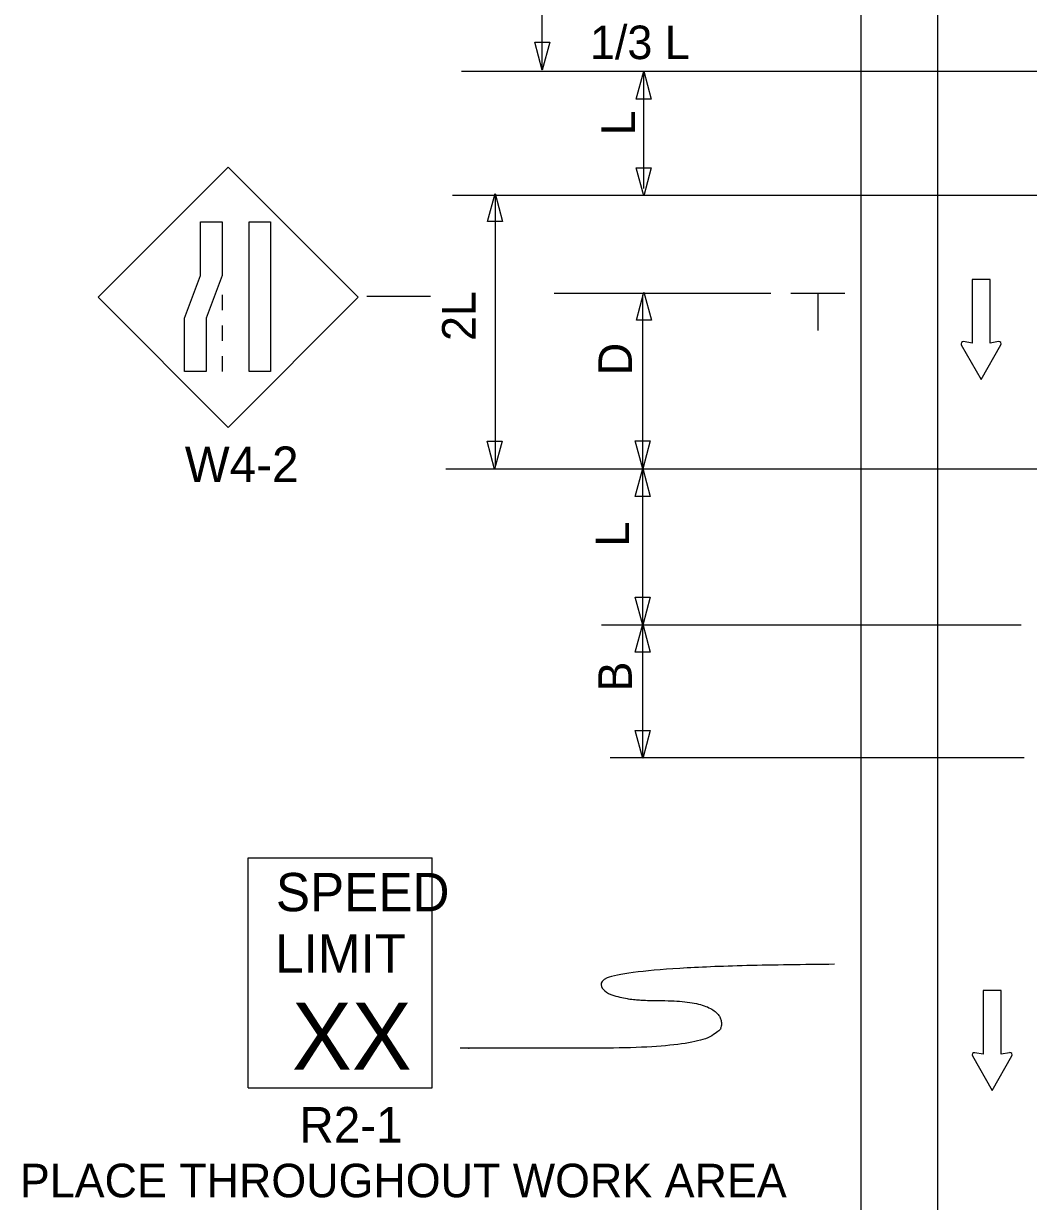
# Model space of a CAD drawing. Extents: x 20837 to 23689, y 414 to 2167.
# Drawn here: x 20938.5 to 21148.4, y 1033.1 to 1279 of the extents above; entities that cross this region are included whole.
import ezdxf

# ---------------------------------------------------------------- set-up
doc = ezdxf.new("R2010")
doc.units = 0
for name, color, linetype in [('MT_SCRATCH_LEVEL_E', 7, 'Continuous'), ('PAVT_EDGE_EX', 7, 'Continuous'), ('TRAFFIC_SIGNS_PR', 7, 'Continuous'), ('TYPICAL_EX', 7, 'Continuous'), ('TYPICAL_TEXT_DIMEN_PR', 7, 'Continuous')]:
    doc.layers.add(name, color=color, linetype=linetype)

msp = doc.modelspace()

# ---------------------------------------------------------------- linework, layer by layer
at = {"layer": 'MT_SCRATCH_LEVEL_E'}
for p, q in [((21140.37, 1225.58), (21136.63, 1225.58)), ((21136.63, 1225.58), (21136.63, 1212.32)), ((21140.37, 1225.58), (21136.63, 1225.58)), ((21136.63, 1225.58), (21136.63, 1212.32)), ((21140.37, 1212.32), (21140.37, 1225.58)), ((21140.37, 1212.32), (21140.37, 1225.58)), ((21136.63, 1212.32), (21134.85, 1212.64)), ((21136.63, 1212.32), (21134.85, 1212.64)), ((21142.15, 1212.64), (21140.37, 1212.32)), ((21142.15, 1212.64), (21140.37, 1212.32)), ((21134.37, 1211.95), (21138.52, 1204.71)), ((21134.37, 1211.95), (21138.52, 1204.71)), ((21138.52, 1204.71), (21142.63, 1211.95)), ((21138.52, 1204.71), (21142.63, 1211.95)), ((21142.68, 1077.11), (21138.94, 1077.11)), ((21138.94, 1077.11), (21138.94, 1063.85)), ((21142.68, 1077.11), (21138.94, 1077.11)), ((21138.94, 1077.11), (21138.94, 1063.85)), ((21142.68, 1063.85), (21142.68, 1077.11)), ((21142.68, 1063.85), (21142.68, 1077.11)), ((21136.69, 1063.48), (21140.83, 1056.24)), ((21136.69, 1063.48), (21140.83, 1056.24)), ((21138.94, 1063.85), (21137.17, 1064.16)), ((21138.94, 1063.85), (21137.17, 1064.16)), ((21140.83, 1056.24), (21144.94, 1063.48)), ((21140.83, 1056.24), (21144.94, 1063.48)), ((21144.46, 1064.16), (21142.68, 1063.85)), ((21144.46, 1064.16), (21142.68, 1063.85))]:
    msp.add_line(p, q, dxfattribs=at)
for centre, start, end in [((21134.78, 1212.18), 80.0362, 209.7731), ((21134.78, 1212.18), 80.0362, 209.7731), ((21142.22, 1212.18), 330.4248, 99.9638), ((21142.22, 1212.18), 330.4248, 99.9638), ((21137.09, 1063.7), 80.0362, 209.7731), ((21137.09, 1063.7), 80.0362, 209.7731), ((21144.54, 1063.71), 330.4248, 99.9638), ((21144.54, 1063.71), 330.4248, 99.9638)]:
    msp.add_arc(centre, 0.463, start, end, dxfattribs=at)
at = {"layer": 'PAVT_EDGE_EX'}
msp.add_line((21129.4, 1637.35), (21129.4, 831.94), dxfattribs=at)
at = {"layer": 'TRAFFIC_SIGNS_PR'}
for p, q in [((20981.2, 1249.03), (20954.05, 1221.88)), ((21008.35, 1221.88), (20981.2, 1249.03)), ((20979.95, 1222.37), (20979.95, 1219.17)), ((20954.05, 1221.88), (20981.2, 1194.73)), ((20981.2, 1194.73), (21008.35, 1221.88)), ((20979.95, 1215.97), (20979.95, 1212.77)), ((20979.95, 1209.57), (20979.95, 1206.37)), ((20985.42, 1104.82), (21023.82, 1104.82)), ((20985.42, 1056.82), (20985.42, 1104.82)), ((21023.82, 1056.82), (21023.82, 1104.82)), ((20985.42, 1056.82), (21023.82, 1056.82))]:
    msp.add_line(p, q, dxfattribs=at)
for points in [[(20979.95, 1237.62), (20979.95, 1226.44), (20976.61, 1217.55), (20976.61, 1206.37), (20972.11, 1206.37), (20972.11, 1217.55), (20975.46, 1226.44), (20975.46, 1237.62)], [(20990.09, 1237.62), (20990.09, 1206.37), (20985.6, 1206.37), (20985.6, 1237.62)]]:
    msp.add_lwpolyline(points, close=True, dxfattribs=at)
at = {"layer": 'TYPICAL_EX'}
msp.add_line((21113.4, 1637.05), (21113.4, 832.24), dxfattribs=at)
at = {"layer": 'TYPICAL_TEXT_DIMEN_PR'}
for p, q in [((21046.82, 1269.4), (21046.82, 1315.73)), ((21046.83, 1269.28), (21045.26, 1275.14)), ((21045.26, 1275.14), (21046.83, 1275.14)), ((21046.83, 1275.14), (21048.4, 1275.14)), ((21048.4, 1275.14), (21046.83, 1269.28)), ((21029.98, 1269.09), (21194.1, 1269.09)), ((21066.47, 1263.27), (21068.04, 1269.13)), ((21068.04, 1269.13), (21069.61, 1263.27)), ((21068.04, 1244.6), (21068.04, 1268.71)), ((21068.04, 1263.27), (21066.47, 1263.27)), ((21069.61, 1263.27), (21068.04, 1263.27)), ((21068.04, 1243.09), (21066.47, 1248.95)), ((21066.47, 1248.95), (21068.04, 1248.95)), ((21068.04, 1248.95), (21069.61, 1248.95)), ((21069.61, 1248.95), (21068.04, 1243.09)), ((21028.1, 1243.22), (21170.08, 1243.22)), ((21035.42, 1237.68), (21036.99, 1243.55)), ((21036.99, 1243.55), (21038.56, 1237.68)), ((21037, 1243.27), (21037, 1186.4)), ((21036.99, 1237.68), (21035.42, 1237.68)), ((21038.56, 1237.68), (21036.99, 1237.68)), ((21049.32, 1222.75), (21094.58, 1222.75)), ((21066.49, 1217.12), (21068.06, 1222.98)), ((21068.06, 1222.98), (21069.63, 1217.12)), ((21098.77, 1222.75), (21110.02, 1222.75)), ((21104.39, 1222.75), (21104.39, 1214.97)), ((21010.2, 1222.13), (21023.48, 1222.13)), ((21067.83, 1185.99), (21067.83, 1222.3)), ((21068.06, 1217.12), (21066.49, 1217.12)), ((21069.63, 1217.12), (21068.06, 1217.12)), ((21036.88, 1185.98), (21035.31, 1191.84)), ((21035.31, 1191.84), (21036.88, 1191.84)), ((21036.88, 1191.84), (21038.45, 1191.84)), ((21038.45, 1191.84), (21036.88, 1185.98)), ((21067.84, 1186.08), (21066.27, 1191.94)), ((21066.27, 1191.94), (21067.84, 1191.94)), ((21067.84, 1191.94), (21069.41, 1191.94)), ((21069.41, 1191.94), (21067.84, 1186.08)), ((21026.68, 1186.1), (21171.95, 1186.1)), ((21066.27, 1180.26), (21067.84, 1186.12)), ((21067.83, 1153.41), (21067.83, 1185.69)), ((21067.84, 1186.12), (21069.41, 1180.26)), ((21067.84, 1180.26), (21066.27, 1180.26)), ((21069.41, 1180.26), (21067.84, 1180.26)), ((21067.84, 1153.4), (21066.27, 1159.26)), ((21066.27, 1159.26), (21067.84, 1159.26)), ((21067.84, 1159.26), (21069.41, 1159.26)), ((21069.41, 1159.26), (21067.84, 1153.4)), ((21059.19, 1153.53), (21146.91, 1153.53)), ((21066.27, 1147.81), (21067.84, 1153.67)), ((21067.83, 1125.89), (21067.83, 1153.5)), ((21067.84, 1153.67), (21069.41, 1147.81)), ((21067.84, 1147.81), (21066.27, 1147.81)), ((21069.41, 1147.81), (21067.84, 1147.81)), ((21067.84, 1125.6), (21066.27, 1131.46)), ((21066.27, 1131.46), (21067.84, 1131.46)), ((21067.84, 1131.46), (21069.41, 1131.46)), ((21069.41, 1131.46), (21067.84, 1125.6)), ((21061.04, 1125.81), (21147.53, 1125.81))]:
    msp.add_line(p, q, dxfattribs=at)
msp.add_open_spline([(21107.89, 1082.61), (21059.09, 1082.29), (21059.09, 1075.03), (21084.27, 1075.03), (21084.27, 1065.12), (21034.62, 1065.12), (21029.69, 1065.12)], degree=2, dxfattribs=at)

# ---------------------------------------------------------------- texts
at = {"layer": 'TRAFFIC_SIGNS_PR'}
for s, height, p in [('W4-2', 7.44, (20972.16, 1183.29)), ('SPEED', 8, (20991.19, 1093.69)), ('LIMIT', 8, (20991.03, 1080.89)), ('XX', 14.031, (20994.54, 1060.58)), ('R2-1', 7.44, (20996.1, 1045.38)), ('PLACE THROUGHOUT WORK AREA', 7, (20937.71, 1033.97))]:
    msp.add_text(s, height=height, dxfattribs=at).set_placement(p)
at = {"layer": 'TYPICAL_TEXT_DIMEN_PR'}
msp.add_text('1/3 L', height=7, dxfattribs=at).set_placement((21056.82, 1271.62))
for s, p in [('L', (21066.19, 1255.71)), ('2L', (21032.9, 1212.77)), ('D', (21065.57, 1205.62)), ('L', (21064.98, 1169.85)), ('B', (21065.56, 1139.58))]:
    msp.add_text(s, height=7, rotation=90, dxfattribs=at).set_placement(p)

doc.saveas('drawing.dxf')
